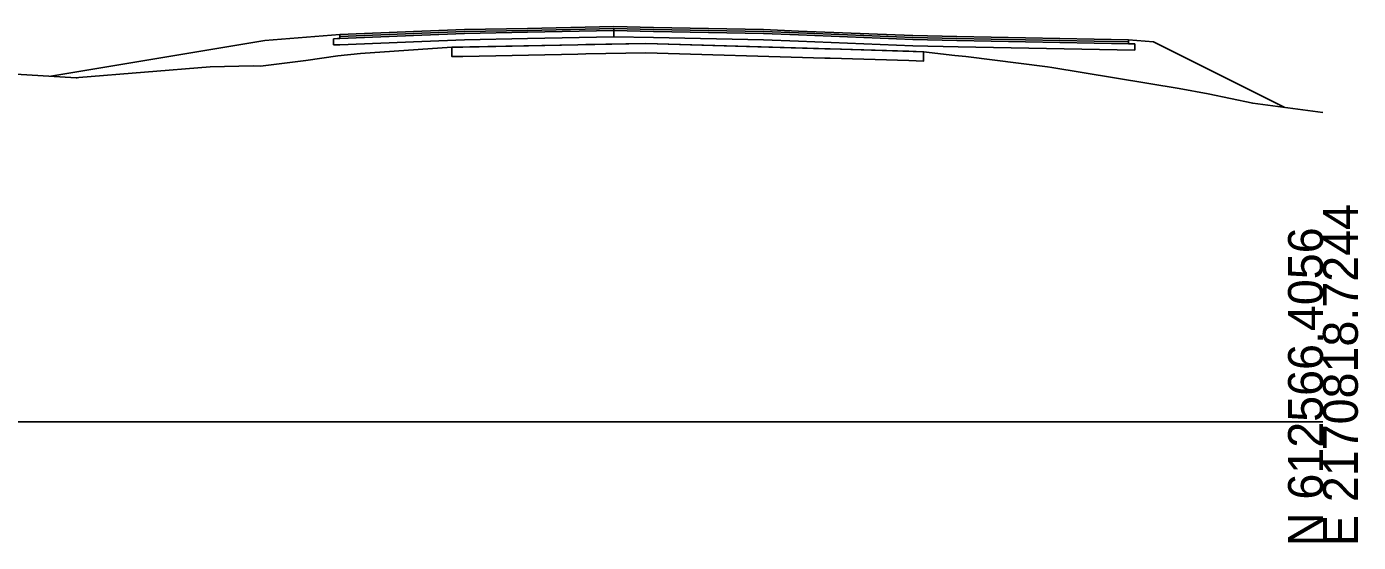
# Model space of a CAD drawing. Extents: x -26 to 1303, y -3010 to 12038.
# Drawn here: x 196 to 302.8, y 8490.3 to 8531.7 of the extents above; entities that cross this region are included whole.
import ezdxf

# ---------------------------------------------------------------- set-up
doc = ezdxf.new("R2010")
doc.units = 0
for name, color, linetype in [('RD_GPK_XS_Cell', 7, 'Continuous'), ('RD_XS_Base', 7, 'Continuous'), ('RD_XS_ExGround', 7, 'Continuous'), ('RD_XS_ExPaveRet', 7, 'Continuous'), ('RD_XS_Greenside', 7, 'Continuous'), ('RD_XS_Pave', 7, 'Continuous'), ('RD_XS_PaveOvlay_CP', 7, 'Continuous'), ('RD_XS_TieSlope', 7, 'Continuous')]:
    doc.layers.add(name, color=color, linetype=linetype)

msp = doc.modelspace()

# ---------------------------------------------------------------- linework, layer by layer
at = {"layer": 'RD_GPK_XS_Cell'}
msp.add_line((150, 8500), (300, 8500), dxfattribs=at)
at = {"layer": 'RD_XS_Base'}
for p, q in [((227.69, 8531.04), (221.09, 8530.78)), ((231.09, 8531.17), (227.69, 8531.04)), ((236.15, 8531.28), (231.09, 8531.17)), ((243.09, 8531.41), (236.15, 8531.28)), ((243.09, 8531.53), (243.09, 8531.57)), ((243.09, 8531.57), (243.09, 8531.39)), ((243.09, 8531.41), (243.09, 8531.53)), ((243.09, 8531.41), (243.09, 8531.41)), ((246.26, 8531.35), (243.09, 8531.41)), ((243.09, 8531.41), (243.09, 8531.41)), ((243.09, 8531.28), (243.09, 8531.41)), ((243.09, 8531.39), (243.09, 8530.91)), ((243.09, 8530.91), (243.09, 8531.28)), ((255.09, 8531.17), (246.26, 8531.35)), ((257.91, 8531.06), (255.09, 8531.17)), ((267.09, 8530.69), (257.91, 8531.06)), ((220.91, 8530.77), (220.59, 8530.76)), ((220.59, 8530.76), (220.59, 8530.58)), ((220.59, 8530.58), (220.59, 8530.26)), ((220.59, 8530.26), (220.91, 8530.27)), ((221.09, 8530.78), (220.91, 8530.77)), ((220.91, 8530.27), (221.09, 8530.28)), ((221.09, 8530.28), (227.69, 8530.54)), ((227.69, 8530.54), (231.09, 8530.67)), ((231.09, 8530.67), (236.15, 8530.78)), ((236.15, 8530.78), (243.09, 8530.91)), ((243.09, 8530.91), (246.26, 8530.85)), ((246.26, 8530.85), (255.09, 8530.67)), ((255.09, 8530.67), (257.91, 8530.56)), ((257.91, 8530.56), (267.09, 8530.19)), ((270.62, 8530.62), (267.09, 8530.69)), ((267.09, 8530.19), (270.72, 8530.12)), ((284.39, 8530.35), (270.62, 8530.62)), ((270.72, 8530.12), (284.89, 8529.84)), ((284.48, 8530.34), (284.39, 8530.35)), ((284.89, 8530.34), (284.48, 8530.34)), ((284.89, 8530.25), (284.89, 8530.34)), ((284.89, 8529.84), (284.89, 8530.25))]:
    msp.add_line(p, q, dxfattribs=at)
at = {"layer": 'RD_XS_ExGround'}
msp.add_lwpolyline([(185.37, 8528.5), (199.93, 8527.63), (200.01, 8527.63), (200.15, 8527.64), (210.7, 8528.51), (214.15, 8528.57), (214.72, 8528.56), (218.38, 8529.01), (220.95, 8529.39), (222.76, 8529.56), (230.09, 8530.07), (240.19, 8530.28), (245.66, 8530.38), (260.46, 8529.94), (267.94, 8529.72), (270.46, 8529.42), (271.35, 8529.33), (277.88, 8528.5), (278.24, 8528.44), (288.47, 8526.76), (290.79, 8526.33), (294.37, 8525.58), (299.59, 8524.89), (300, 8524.83)], dxfattribs=at)
at = {"layer": 'RD_XS_ExPaveRet'}
for points in [[(266.77, 8529.75), (260.46, 8529.94), (260.01, 8529.95), (245.66, 8530.38), (240.84, 8530.29), (240.19, 8530.28), (230.96, 8530.09), (230.09, 8530.07), (230.09, 8529.98), (230.09, 8529.32), (230.96, 8529.34), (240.19, 8529.53), (240.84, 8529.54), (245.66, 8529.63), (260.01, 8529.2), (260.46, 8529.19), (266.77, 8529), (267.94, 8528.97), (267.94, 8528.97), (267.94, 8529.72), (266.77, 8529.75)], [(240.84, 8530.29), (240.19, 8530.28), (230.96, 8530.09), (230.09, 8530.07)], [(230.09, 8530.07), (230.09, 8529.98), (230.09, 8529.32), (230.96, 8529.34), (240.19, 8529.53), (240.84, 8529.54), (245.66, 8529.63), (260.01, 8529.2), (260.46, 8529.19), (266.77, 8529), (267.94, 8528.97), (267.94, 8528.97), (267.94, 8529.72)], [(260.01, 8529.95), (245.66, 8530.38), (240.84, 8530.29)], [(267.94, 8529.72), (266.77, 8529.75), (260.46, 8529.94), (260.01, 8529.95)]]:
    msp.add_lwpolyline(points, dxfattribs=at)
at = {"layer": 'RD_XS_Greenside'}
for p, q in [((215.09, 8530.61), (197.91, 8527.75)), ((286.39, 8530.5), (296.93, 8525.24))]:
    msp.add_line(p, q, dxfattribs=at)
at = {"layer": 'RD_XS_Pave'}
for p, q in [((227.69, 8531.36), (221.09, 8531.09)), ((227.69, 8531.2), (221.09, 8530.93)), ((221.09, 8530.93), (227.69, 8531.2)), ((221.09, 8531.09), (221.09, 8531.04)), ((221.09, 8530.78), (227.69, 8531.04)), ((221.09, 8531.04), (221.09, 8530.93)), ((231.09, 8531.49), (227.69, 8531.36)), ((231.09, 8531.33), (227.69, 8531.2)), ((227.69, 8531.2), (231.09, 8531.33)), ((227.69, 8531.04), (231.09, 8531.17)), ((236.15, 8531.59), (231.09, 8531.49)), ((236.15, 8531.43), (231.09, 8531.33)), ((231.09, 8531.33), (236.15, 8531.43)), ((231.09, 8531.17), (236.15, 8531.28)), ((243.09, 8531.73), (236.15, 8531.59)), ((243.09, 8531.57), (236.15, 8531.43)), ((236.15, 8531.43), (243.09, 8531.57)), ((236.15, 8531.28), (243.09, 8531.41)), ((246.26, 8531.67), (243.09, 8531.73)), ((243.09, 8531.53), (243.09, 8531.57)), ((243.09, 8531.57), (246.26, 8531.51)), ((246.26, 8531.51), (243.09, 8531.57)), ((243.09, 8531.57), (243.09, 8531.57)), ((243.09, 8531.57), (243.09, 8531.57)), ((243.09, 8531.57), (243.09, 8531.53)), ((243.09, 8531.41), (243.09, 8531.53)), ((243.09, 8531.53), (243.09, 8531.41)), ((243.09, 8531.41), (243.09, 8531.41)), ((243.09, 8531.41), (243.09, 8531.41)), ((243.09, 8531.41), (246.26, 8531.35)), ((255.09, 8531.49), (246.26, 8531.67)), ((246.26, 8531.51), (255.09, 8531.33)), ((255.09, 8531.33), (246.26, 8531.51)), ((246.26, 8531.35), (255.09, 8531.17)), ((257.91, 8531.38), (255.09, 8531.49)), ((255.09, 8531.33), (257.91, 8531.22)), ((257.91, 8531.22), (255.09, 8531.33)), ((255.09, 8531.17), (257.91, 8531.06)), ((267.09, 8531.01), (257.91, 8531.38)), ((257.91, 8531.22), (267.09, 8530.85)), ((267.09, 8530.85), (257.91, 8531.22)), ((257.91, 8531.06), (267.09, 8530.69)), ((270.62, 8530.94), (267.09, 8531.01)), ((221.09, 8530.93), (221.09, 8530.88)), ((221.09, 8530.88), (221.09, 8530.78)), ((267.09, 8530.85), (270.62, 8530.78)), ((270.62, 8530.78), (267.09, 8530.85)), ((267.09, 8530.69), (270.62, 8530.62)), ((284.39, 8530.66), (270.62, 8530.94)), ((270.62, 8530.78), (284.39, 8530.51)), ((284.39, 8530.51), (270.62, 8530.78)), ((270.62, 8530.62), (284.39, 8530.35)), ((284.39, 8530.64), (284.39, 8530.66)), ((284.39, 8530.51), (284.39, 8530.64)), ((284.39, 8530.48), (284.39, 8530.51)), ((284.39, 8530.35), (284.39, 8530.48))]:
    msp.add_line(p, q, dxfattribs=at)
at = {"layer": 'RD_XS_PaveOvlay_CP'}
for p, q in [((227.69, 8531.36), (221.09, 8531.09)), ((231.09, 8531.49), (227.69, 8531.36)), ((236.15, 8531.59), (231.09, 8531.49)), ((243.09, 8531.73), (236.15, 8531.59)), ((246.26, 8531.67), (243.09, 8531.73)), ((255.09, 8531.49), (246.26, 8531.67)), ((257.91, 8531.38), (255.09, 8531.49)), ((267.09, 8531.01), (257.91, 8531.38)), ((270.62, 8530.94), (267.09, 8531.01)), ((284.39, 8530.66), (270.62, 8530.94))]:
    msp.add_line(p, q, dxfattribs=at)
at = {"layer": 'RD_XS_TieSlope'}
for p, q in [((221.09, 8531.09), (215.09, 8530.61)), ((284.39, 8530.66), (286.39, 8530.5))]:
    msp.add_line(p, q, dxfattribs=at)

# ---------------------------------------------------------------- texts
at = {"layer": 'RD_GPK_XS_Cell'}
for s, p in [('E 2170818.7244', (302.8, 8490)), ('N 612566.4056', (300, 8490))]:
    msp.add_text(s, height=2.8, rotation=90, dxfattribs=at).set_placement(p)

doc.saveas('drawing.dxf')
